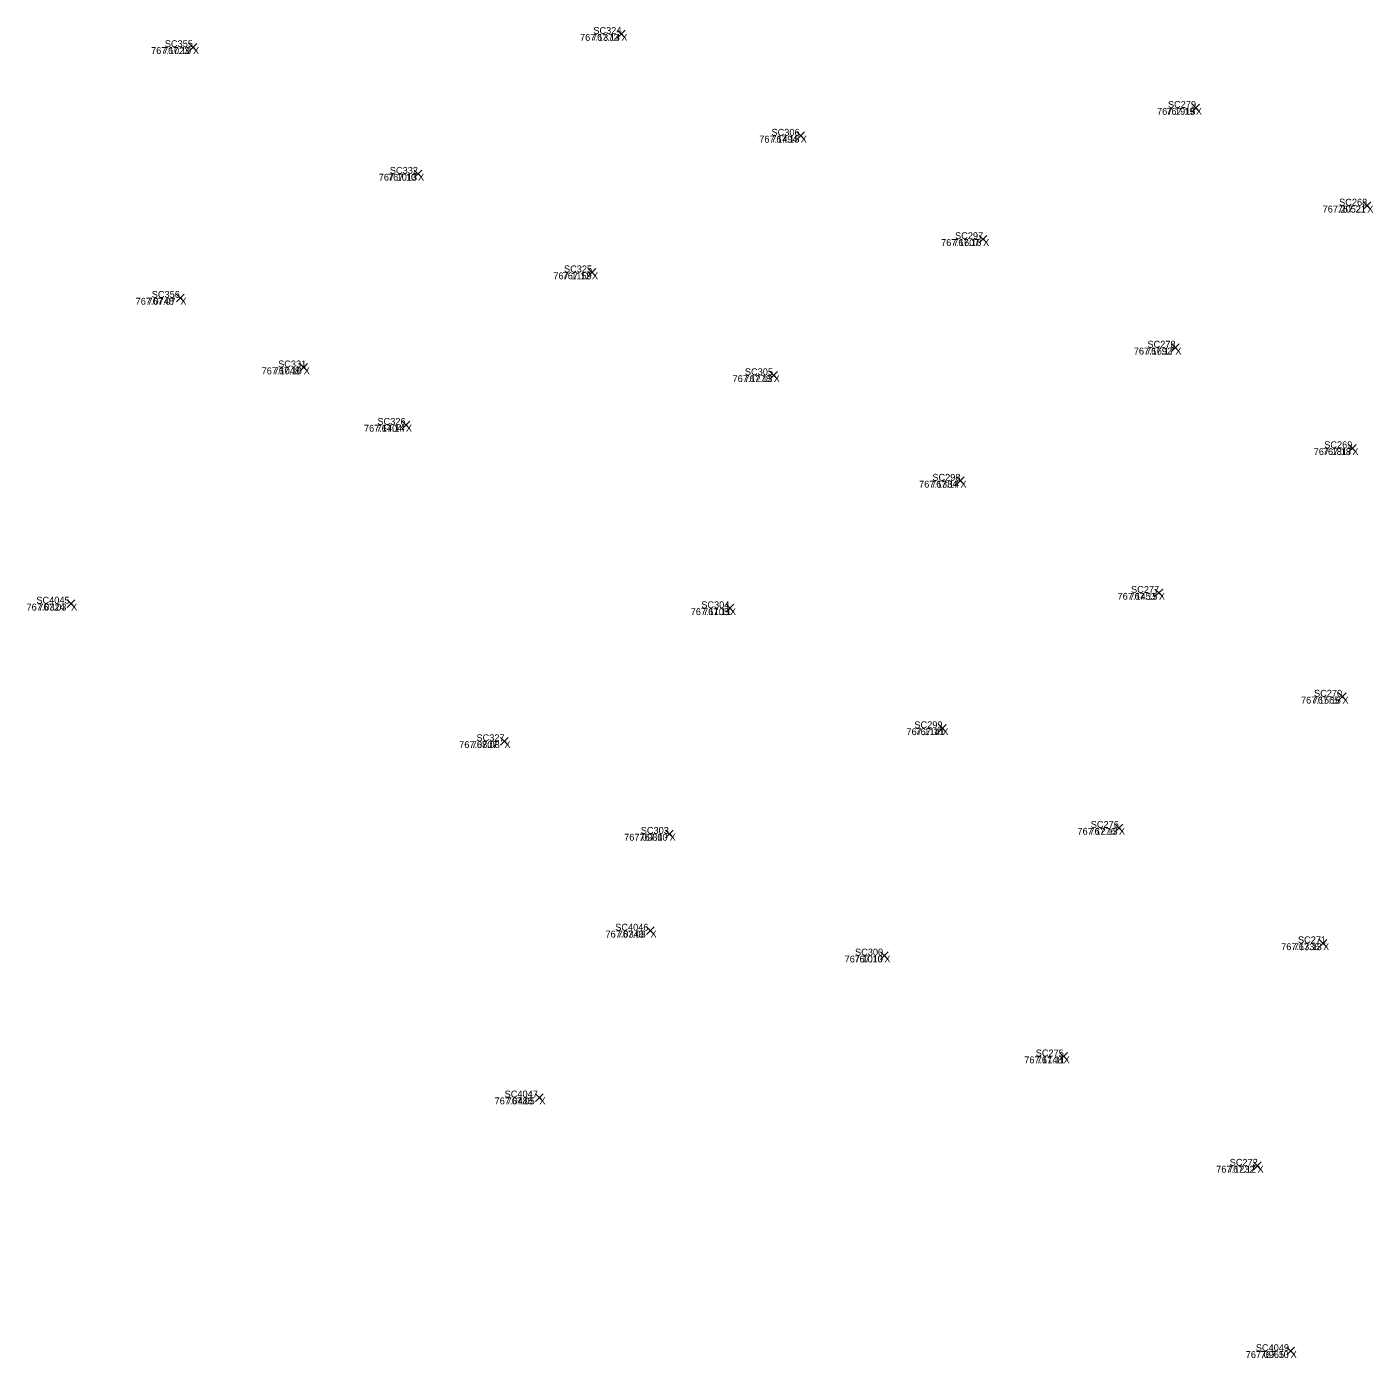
# Model space of a CAD drawing. Extents: x 1845019 to 1877956, y 680444 to 701081.
# Drawn here: x 1857650.72 to 1857662.47, y 694265.46 to 694277.07 of the extents above; entities that cross this region are included whole.
import ezdxf

# ---------------------------------------------------------------- set-up
doc = ezdxf.new("R2010")
doc.units = 0
for name, color, linetype in [('SV_X_Random_Point', 7, 'Continuous'), ('SV_X_Text_Comment', 7, 'Continuous'), ('SV_X_Text_Elevation', 7, 'Continuous'), ('SV_X_Text_Name', 7, 'Continuous')]:
    doc.layers.add(name, color=color, linetype=linetype)

msp = doc.modelspace()

# ---------------------------------------------------------------- linework, layer by layer
at = {"layer": 'SV_X_Random_Point'}
for p, q in [((1857655.879, 694276.976), (1857655.945, 694277.043)), ((1857655.879, 694277.043), (1857655.945, 694276.976)), ((1857655.879, 694276.976), (1857655.945, 694277.043)), ((1857655.879, 694277.043), (1857655.945, 694276.976)), ((1857652.14, 694276.86), (1857652.207, 694276.927)), ((1857652.14, 694276.927), (1857652.207, 694276.86)), ((1857652.14, 694276.86), (1857652.207, 694276.927)), ((1857652.14, 694276.927), (1857652.207, 694276.86)), ((1857660.893, 694276.331), (1857660.959, 694276.397)), ((1857660.893, 694276.397), (1857660.959, 694276.331)), ((1857660.893, 694276.331), (1857660.959, 694276.397)), ((1857660.893, 694276.397), (1857660.959, 694276.331)), ((1857657.444, 694276.088), (1857657.511, 694276.155)), ((1857657.444, 694276.155), (1857657.511, 694276.088)), ((1857657.444, 694276.088), (1857657.511, 694276.155)), ((1857657.444, 694276.155), (1857657.511, 694276.088)), ((1857654.104, 694275.756), (1857654.171, 694275.822)), ((1857654.104, 694275.822), (1857654.171, 694275.756)), ((1857654.104, 694275.756), (1857654.171, 694275.822)), ((1857654.104, 694275.822), (1857654.171, 694275.756)), ((1857662.388, 694275.477), (1857662.455, 694275.544)), ((1857662.388, 694275.544), (1857662.455, 694275.477)), ((1857662.388, 694275.477), (1857662.455, 694275.544)), ((1857662.388, 694275.544), (1857662.455, 694275.477)), ((1857659.036, 694275.186), (1857659.103, 694275.252)), ((1857659.036, 694275.252), (1857659.103, 694275.186)), ((1857659.036, 694275.186), (1857659.103, 694275.252)), ((1857659.036, 694275.252), (1857659.103, 694275.186)), ((1857655.623, 694274.896), (1857655.689, 694274.962)), ((1857655.623, 694274.962), (1857655.689, 694274.896)), ((1857655.623, 694274.896), (1857655.689, 694274.962)), ((1857655.623, 694274.962), (1857655.689, 694274.896)), ((1857652.03, 694274.673), (1857652.096, 694274.74)), ((1857652.03, 694274.74), (1857652.096, 694274.673)), ((1857652.03, 694274.673), (1857652.096, 694274.74)), ((1857652.03, 694274.74), (1857652.096, 694274.673)), ((1857660.714, 694274.238), (1857660.78, 694274.305)), ((1857660.714, 694274.305), (1857660.78, 694274.238)), ((1857660.714, 694274.238), (1857660.78, 694274.305)), ((1857660.714, 694274.305), (1857660.78, 694274.238)), ((1857653.107, 694274.067), (1857653.173, 694274.134)), ((1857653.107, 694274.134), (1857653.173, 694274.067)), ((1857653.107, 694274.067), (1857653.173, 694274.134)), ((1857653.107, 694274.134), (1857653.173, 694274.067)), ((1857657.209, 694273.998), (1857657.276, 694274.065)), ((1857657.209, 694274.065), (1857657.276, 694273.998)), ((1857657.209, 694273.998), (1857657.276, 694274.065)), ((1857657.209, 694274.065), (1857657.276, 694273.998)), ((1857653.999, 694273.565), (1857654.066, 694273.632)), ((1857653.999, 694273.632), (1857654.066, 694273.565)), ((1857653.999, 694273.565), (1857654.066, 694273.632)), ((1857653.999, 694273.632), (1857654.066, 694273.565)), ((1857662.259, 694273.361), (1857662.325, 694273.428)), ((1857662.259, 694273.428), (1857662.325, 694273.361)), ((1857662.259, 694273.361), (1857662.325, 694273.428)), ((1857662.259, 694273.428), (1857662.325, 694273.361)), ((1857658.838, 694273.077), (1857658.905, 694273.144)), ((1857658.838, 694273.144), (1857658.905, 694273.077)), ((1857658.838, 694273.077), (1857658.905, 694273.144)), ((1857658.838, 694273.144), (1857658.905, 694273.077)), ((1857660.57, 694272.1), (1857660.637, 694272.166)), ((1857660.57, 694272.166), (1857660.637, 694272.1)), ((1857660.57, 694272.1), (1857660.637, 694272.166)), ((1857660.57, 694272.166), (1857660.637, 694272.1)), ((1857651.076, 694272.005), (1857651.143, 694272.072)), ((1857651.076, 694272.072), (1857651.143, 694272.005)), ((1857651.076, 694272.005), (1857651.143, 694272.072)), ((1857651.076, 694272.072), (1857651.143, 694272.005)), ((1857656.827, 694271.966), (1857656.893, 694272.033)), ((1857656.827, 694272.033), (1857656.893, 694271.966)), ((1857656.827, 694271.966), (1857656.893, 694272.033)), ((1857656.827, 694272.033), (1857656.893, 694271.966)), ((1857662.172, 694271.194), (1857662.239, 694271.26)), ((1857662.172, 694271.26), (1857662.239, 694271.194)), ((1857662.172, 694271.194), (1857662.239, 694271.26)), ((1857662.172, 694271.26), (1857662.239, 694271.194)), ((1857658.681, 694270.919), (1857658.748, 694270.985)), ((1857658.681, 694270.985), (1857658.748, 694270.919)), ((1857658.681, 694270.919), (1857658.748, 694270.985)), ((1857658.681, 694270.985), (1857658.748, 694270.919)), ((1857654.859, 694270.805), (1857654.925, 694270.872)), ((1857654.859, 694270.872), (1857654.925, 694270.805)), ((1857654.859, 694270.805), (1857654.925, 694270.872)), ((1857654.859, 694270.872), (1857654.925, 694270.805)), ((1857660.222, 694270.049), (1857660.288, 694270.116)), ((1857660.222, 694270.116), (1857660.288, 694270.049)), ((1857660.222, 694270.049), (1857660.288, 694270.116)), ((1857660.222, 694270.116), (1857660.288, 694270.049)), ((1857656.299, 694269.997), (1857656.366, 694270.064)), ((1857656.299, 694270.064), (1857656.366, 694269.997)), ((1857656.299, 694269.997), (1857656.366, 694270.064)), ((1857656.299, 694270.064), (1857656.366, 694269.997)), ((1857656.132, 694269.153), (1857656.199, 694269.219)), ((1857656.132, 694269.219), (1857656.199, 694269.153)), ((1857656.132, 694269.153), (1857656.199, 694269.219)), ((1857656.132, 694269.219), (1857656.199, 694269.153)), ((1857662.004, 694269.043), (1857662.07, 694269.11)), ((1857662.004, 694269.11), (1857662.07, 694269.043)), ((1857662.004, 694269.043), (1857662.07, 694269.11)), ((1857662.004, 694269.11), (1857662.07, 694269.043)), ((1857658.175, 694268.935), (1857658.242, 694269.002)), ((1857658.175, 694269.002), (1857658.242, 694268.935)), ((1857658.175, 694268.935), (1857658.242, 694269.002)), ((1857658.175, 694269.002), (1857658.242, 694268.935)), ((1857659.738, 694268.056), (1857659.805, 694268.123)), ((1857659.738, 694268.123), (1857659.805, 694268.056)), ((1857659.738, 694268.056), (1857659.805, 694268.123)), ((1857659.738, 694268.123), (1857659.805, 694268.056)), ((1857655.163, 694267.697), (1857655.23, 694267.764)), ((1857655.163, 694267.764), (1857655.23, 694267.697)), ((1857655.163, 694267.697), (1857655.23, 694267.764)), ((1857655.163, 694267.764), (1857655.23, 694267.697)), ((1857661.43, 694267.101), (1857661.497, 694267.168)), ((1857661.43, 694267.168), (1857661.497, 694267.101)), ((1857661.43, 694267.101), (1857661.497, 694267.168)), ((1857661.43, 694267.168), (1857661.497, 694267.101)), ((1857661.72, 694265.485), (1857661.787, 694265.552)), ((1857661.72, 694265.552), (1857661.787, 694265.485)), ((1857661.72, 694265.485), (1857661.787, 694265.552)), ((1857661.72, 694265.552), (1857661.787, 694265.485))]:
    msp.add_line(p, q, dxfattribs=at)

# ---------------------------------------------------------------- texts
at = {"layer": 'SV_X_Text_Comment'}
for p in [(1857655.912, 694276.949), (1857652.174, 694276.834), (1857660.926, 694276.304), (1857657.478, 694276.061), (1857654.138, 694275.729), (1857662.422, 694275.451), (1857659.07, 694275.159), (1857655.656, 694274.869), (1857652.063, 694274.647), (1857660.747, 694274.212), (1857653.14, 694274.04), (1857657.242, 694273.972), (1857654.032, 694273.539), (1857662.292, 694273.335), (1857658.872, 694273.051), (1857660.604, 694272.073), (1857651.11, 694271.979), (1857656.86, 694271.939), (1857662.206, 694271.167), (1857658.714, 694270.892), (1857654.892, 694270.779), (1857656.333, 694269.971), (1857660.255, 694270.023), (1857656.166, 694269.126), (1857662.037, 694269.016), (1857658.208, 694268.909), (1857659.772, 694268.029), (1857655.197, 694267.671), (1857661.464, 694267.075), (1857661.754, 694265.458)]:
    msp.add_text('X', height=0.06, dxfattribs=at).set_placement(p)
at = {"layer": 'SV_X_Text_Elevation'}
for s, p in [('767.1372', (1857655.552, 694276.949)), ('767.14', (1857655.656, 694276.949)), ('767.1023', (1857651.808, 694276.834)), ('767.10', (1857651.912, 694276.834)), ('767.1915', (1857660.588, 694276.304)), ('767.19', (1857660.669, 694276.304)), ('767.1494', (1857657.116, 694276.061)), ('767.15', (1857657.221, 694276.061)), ('767.1013', (1857653.795, 694275.729)), ('767.10', (1857653.876, 694275.729)), ('767.2052', (1857662.033, 694275.451)), ('767.21', (1857662.165, 694275.451)), ('767.1607', (1857658.703, 694275.159)), ('767.16', (1857658.809, 694275.159)), ('767.1159', (1857655.319, 694274.869)), ('767.12', (1857655.4, 694274.869)), ('767.0748', (1857651.673, 694274.647)), ('767.07', (1857651.777, 694274.647)), ('767.1692', (1857660.385, 694274.212)), ('767.17', (1857660.491, 694274.212)), ('767.1048', (1857652.773, 694274.04)), ('767.10', (1857652.878, 694274.04)), ('767.1278', (1857656.883, 694273.972)), ('767.13', (1857656.986, 694273.972)), ('767.1404', (1857653.666, 694273.539)), ('767.14', (1857653.776, 694273.539)), ('767.1817', (1857661.955, 694273.335)), ('767.18', (1857662.035, 694273.335)), ('767.1384', (1857658.511, 694273.051)), ('767.14', (1857658.616, 694273.051)), ('767.1453', (1857660.243, 694272.073)), ('767.15', (1857660.347, 694272.073)), ('767.0324', (1857650.721, 694271.979)), ('767.03', (1857650.824, 694271.979)), ('767.1105', (1857656.518, 694271.939)), ('767.11', (1857656.626, 694271.939)), ('767.1565', (1857661.844, 694271.167)), ('767.16', (1857661.946, 694271.167)), ('767.1141', (1857658.401, 694270.892)), ('767.11', (1857658.48, 694270.892)), ('767.0807', (1857654.497, 694270.779)), ('767.08', (1857654.606, 694270.779)), ('767.0980', (1857655.937, 694269.971)), ('767.10', (1857656.071, 694269.971)), ('767.1276', (1857659.893, 694270.023)), ('767.13', (1857659.998, 694270.023)), ('767.0343', (1857655.774, 694269.126)), ('767.03', (1857655.88, 694269.126)), ('767.1336', (1857661.671, 694269.016)), ('767.13', (1857661.78, 694269.016)), ('767.1010', (1857657.861, 694268.909)), ('767.10', (1857657.947, 694268.909)), ('767.1140', (1857659.429, 694268.029)), ('767.11', (1857659.538, 694268.029)), ('767.0488', (1857654.806, 694267.671)), ('767.05', (1857654.911, 694267.671)), ('767.1232', (1857661.104, 694267.075)), ('767.12', (1857661.207, 694267.075)), ('767.0965', (1857661.362, 694265.458)), ('767.10', (1857661.492, 694265.458))]:
    msp.add_text(s, height=0.06, dxfattribs=at).set_placement(p)
at = {"layer": 'SV_X_Text_Name'}
for s, p in [('SC324', (1857655.668, 694277.009)), ('SC324', (1857655.668, 694277.009)), ('SC355', (1857651.928, 694276.894)), ('SC355', (1857651.928, 694276.894)), ('SC279', (1857660.683, 694276.364)), ('SC279', (1857660.683, 694276.364)), ('SC306', (1857657.223, 694276.121)), ('SC306', (1857657.223, 694276.121)), ('SC332', (1857653.892, 694275.789)), ('SC332', (1857653.892, 694275.789)), ('SC268', (1857662.177, 694275.511)), ('SC268', (1857662.177, 694275.511)), ('SC297', (1857658.825, 694275.219)), ('SC297', (1857658.825, 694275.219)), ('SC325', (1857655.412, 694274.929)), ('SC325', (1857655.412, 694274.929)), ('SC356', (1857651.814, 694274.707)), ('SC356', (1857651.814, 694274.707)), ('SC278', (1857660.504, 694274.272)), ('SC278', (1857660.504, 694274.272)), ('SC331', (1857652.917, 694274.1)), ('SC331', (1857652.917, 694274.1)), ('SC305', (1857656.991, 694274.032)), ('SC305', (1857656.991, 694274.032)), ('SC326', (1857653.784, 694273.599)), ('SC326', (1857653.784, 694273.599)), ('SC269', (1857662.047, 694273.395)), ('SC269', (1857662.047, 694273.395)), ('SC298', (1857658.627, 694273.111)), ('SC298', (1857658.627, 694273.111)), ('SC4045', (1857650.807, 694272.039)), ('SC4045', (1857650.807, 694272.039)), ('SC277', (1857660.361, 694272.133)), ('SC277', (1857660.361, 694272.133)), ('SC304', (1857656.61, 694271.999)), ('SC304', (1857656.61, 694271.999)), ('SC270', (1857661.958, 694271.227)), ('SC270', (1857661.958, 694271.227)), ('SC299', (1857658.47, 694270.952)), ('SC299', (1857658.47, 694270.952)), ('SC327', (1857654.648, 694270.839)), ('SC327', (1857654.648, 694270.839)), ('SC303', (1857656.082, 694270.031)), ('SC303', (1857656.082, 694270.031)), ('SC276', (1857660.009, 694270.083)), ('SC276', (1857660.009, 694270.083)), ('SC4046', (1857655.859, 694269.186)), ('SC4046', (1857655.859, 694269.186)), ('SC300', (1857657.952, 694268.969)), ('SC300', (1857657.952, 694268.969)), ('SC271', (1857661.817, 694269.076)), ('SC271', (1857661.818, 694269.076)), ('SC275', (1857659.529, 694268.089)), ('SC275', (1857659.529, 694268.089)), ('SC4047', (1857654.894, 694267.731)), ('SC4047', (1857654.894, 694267.731)), ('SC272', (1857661.222, 694267.135)), ('SC272', (1857661.222, 694267.135)), ('SC4049', (1857661.45, 694265.518)), ('SC4049', (1857661.45, 694265.518))]:
    msp.add_text(s, height=0.06, dxfattribs=at).set_placement(p)

doc.saveas('drawing.dxf')
